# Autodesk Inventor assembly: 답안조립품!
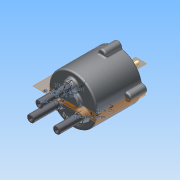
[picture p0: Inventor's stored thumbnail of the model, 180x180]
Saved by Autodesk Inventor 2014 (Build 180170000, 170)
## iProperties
Created: 2015-09
Part Number: 답안조립품!
Document SubType Name: Assembly
Designer: study
Mass: 1565.66 g
Surface Area: 1801.32 cm^2
Volume: 438.544 cm^3
Density: 3.57013 g/cm^3
Author: study
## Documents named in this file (14)
- C:\Users\study\Desktop\350916V1012\답안조립품!.iam
- C:\Users\study\Desktop\350916V1012\몸체.ipt
- C:\Users\study\Desktop\350916V1012\메인 축.ipt
- C:\Users\study\Desktop\350916V1012\판캠.ipt
- C:\Users\study\Desktop\350916V1012\멈춤링 10 x 1.ipt
- C:\Users\study\Desktop\350916V1012\멈춤링 22 x 1.2.ipt
- C:\Users\study\Desktop\350916V1012\슬라이드 축.ipt
- C:\Users\study\Desktop\350916V1012\베어링 NA 4900.ipt
- C:\Users\study\Desktop\350916V1012\오일실.ipt
- C:\Users\study\Desktop\350916V1012\커버.ipt
- C:\Users\study\Desktop\350916V1012\M5x0.8x20.ipt
- C:\Users\study\Desktop\350916V1012\가변스프링.ipt
- C:\Users\study\Desktop\350916V1012\가변스프링2.ipt
- C:\Users\study\Desktop\350916V1012\가변스프링3.ipt
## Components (7 placed, 4 different names)
1. 가변스프링:1
2. 가변스프링2:1
3. 가변스프링3:1
4. M5x0.8x20:1
5. M5x0.8x20:2
6. M5x0.8x20:3
7. M5x0.8x20:4
